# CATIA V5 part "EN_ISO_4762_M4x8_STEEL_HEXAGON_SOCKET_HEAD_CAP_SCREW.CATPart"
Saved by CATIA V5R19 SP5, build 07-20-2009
Part number: EN ISO 4762 SCREW M4x8 STEEL HEXAGON SOCKET HEAD CAP
Publications: "Mating Face", "Axis"
Bounding box of the stored display mesh (mm): x -8 to 4, y -3.5 to 3.5, z -3.329 to 3.329
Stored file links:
  Z:\UA\ATLAS\atlascar\ServoPiloto\dir\suportePotenciometro\V2\EN_ISO_4762_M4x8_STEEL_HEXAGON_SOCKET_HEAD_CAP_SCREW.CATPart
  Z:\programs_vbox\Dassault Systemes\B19\intel_a\startup\components\MechanicalStandardParts\EN_Standards\Design_Tables\EN_ISO_4762_HEXAGON_SOCKET_HEAD_CAP_SCREW.txt
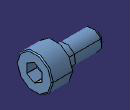
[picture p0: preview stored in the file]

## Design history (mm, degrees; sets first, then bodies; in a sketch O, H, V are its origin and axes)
Parameters
  d_dia = 4 mm
  l_nom = 8 mm
  k_head_depth_max = 4 mm
  s_nom = 3 mm
  r_min = 0.2 mm
  ds_max = 4 mm
  e = 3.443 mm
  t_min = 2 mm
  p_pitch = 0.7 mm
  Threading = 5.9 mm
  dk_max = 7 mm
Body1 "PartBody" (main body)
  Sketch1 on yz-plane, origin (0, 0, 0), H (0, 1, 0), V (0, 0, 1)
    circle A1 centre (0, 0) radius 3.5
    radius A1 = 3.5 {= dk_max /2}
  Pad1: profile Sketch1, direction (1, 0, 0), length 4 {= k_head_depth_max}
  Fillet1: radius 0.2 {= r_min}, on edge [face of Pad1 | face of Pad1]
  Body2
    Sketch2 on face of Pad1, origin (4, 0, 0), H (0, 1, 0), V (0, 0, 1)
      point P1 (1.5, -0.866)
      point P2 (1.5, 0.866)
      point P3 (0, 1.7321)
      point P4 (-1.5, 0.866)
      point P5 (-1.5, -0.866)
      point P6 (0, -1.7321)
      point P7 (1.5, 0)
      line L1 (1.5, -0.866) -> (1.5, 0.866)
      line L2 (1.5, 0.866) -> (0, 1.7321)
      line L3 (0, 1.7321) -> (-1.5, 0.866)
      line L4 (-1.5, 0.866) -> (-1.5, -0.866)
      line L5 (-1.5, -0.866) -> (0, -1.7321)
      line L6 (0, -1.7321) -> (1.5, -0.866)
      construction line L7 (0, 0) -> (1.5, 0)
      construction circle A1 centre (0, 0) radius 1.7321
      construction arc A2 centre (-1.5, -0.866) radius 1.7321 from (-1.5, 0.866) to (0, -1.7321) cw
      construction arc A3 centre (1.5, 0.866) radius 1.7321 from (0, 1.7321) to (1.5, -0.866) ccw
      point P8 (-1.5, -0.866)
      point P9 (1.5, 0.866)
      distance L1 L4 = 3 {= s_nom}
      horizontal: L7 H
      coincidence: A1 P1, A1 P2, A1 P3, A1 P4, A1 P5, A1 P6, A2 P4, A2 P6, A2 O, P8 P5, A3 P3, A3 P1, A3 O, P9 P2
      midpoint: P7 L1
    Pad2: profile Sketch2, direction (-1, 0, 0), length 2.9922 {= t_min +(e /3.47)}
    Body3
      Sketch3 on zx-plane, origin (0, 0, 0), H (-1, 0, 0), V (0, 0, 1)
        point P1 (-1.0061, 0)
        line L1 (-1.0061, 0) -> (-2, 1.7215)
        line L2 (-2, 1.7215) -> (-4, 1.7215)
        line L3 (-4, 1.7215) -> (-4, 0)
        axis line L4 (-46.2384, 0) -> (26.3409, 0)
        reference projected line E1 (-4, -6.9227) -> (-4, 6.9227) from edge [face of Pad2 | face of Pad2]
        length L2 = 2 {= t_min}
        angle L1 L4 = 60
        distance L2 L4 = 1.7215 {= e /2}
        horizontal: L2 H, L4 H
        perpendicularity: L3 L2
        fix: L4
        coincidence: L3 E1, P1 L4
      Shaft1: profile Sketch3, axis Sketch3.L4, angle 360
    Intersect1: tool Body3
  Remove1: tool Body2
  Sketch4 on xy-plane, origin (0, 0, 0), H (1, 0, 0), V (0, 1, 0)
    line L1 (0, 0) -> (0, 2)
    line L2 (0, 2) -> (-2.1, 2)
    line L3 (-2.1, 2) -> (-2.1, 1.9512)
    line L4 (-2.1, 1.9512) -> (-8, 1.9512)
    line L5 (-8, 1.9512) -> (-8, 0)
    axis line L6 (-192.3446, 0) -> (99.1594, 0)
    distance L5 L1 = 8 {= l_nom}
    distance L3 L5 = 5.9 {= Threading}
    distance L2 L6 = 2 {= ds_max /2}
    distance L4 L6 = 1.9512 {= d_dia /2.05}
    vertical: L1 V, L3 V, L5 V
    horizontal: L2 H, L4 H, L6 H
    fix: L6
  Shaft2: profile Sketch4, axis Sketch4.L6, angle 360
  Fillet2: radius 0.2 {= r_min}, on edge [face of Shaft2 | face of Pad1]
  Chamfer1: length 0.7 {= p_pitch}, angle 45, on edge [face of Shaft2 | face of Shaft2]
  Thread1: diameter 3.9024 {= d_dia /1.025}, depth 5.9 {= Threading}, pitch 1, on face of Shaft2, from face of Shaft2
